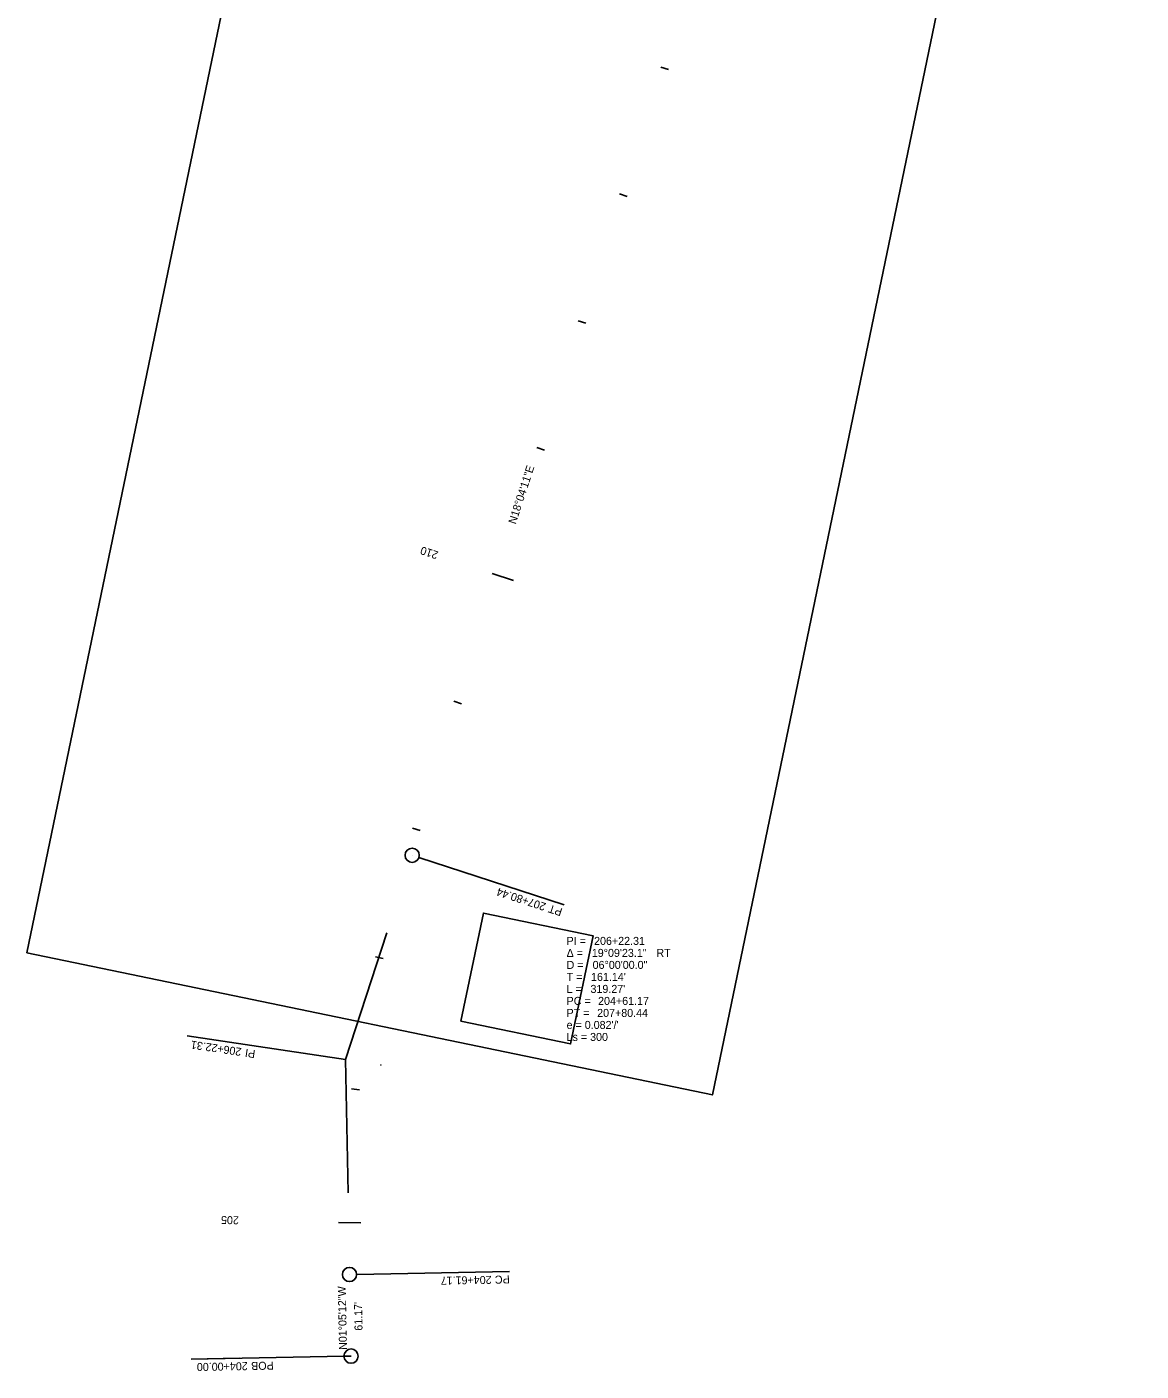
# Model space of a CAD drawing. Extents: x 1802364 to 1804577, y 572742 to 575010.
# Drawn here: x 1802960 to 1803796, y 572742 to 573749 of the extents above; entities that cross this region are included whole.
import ezdxf

# ---------------------------------------------------------------- set-up
doc = ezdxf.new("R2010")
doc.units = 0
for name, color, linetype in [('_CIVIL_CONSTRUCTION', 7, 'Continuous'), ('MOD_COR', 7, 'Continuous'), ('MOD_COR_TemplateDrop', 7, 'Continuous'), ('MOD_Points', 7, 'Continuous')]:
    doc.layers.add(name, color=color, linetype=linetype)

msp = doc.modelspace()

# ---------------------------------------------------------------- linework, layer by layer
at = {"layer": '_CIVIL_CONSTRUCTION'}
for p, q in [((1803435.4, 573719.1), (1803441.1, 573717.3)), ((1803404.4, 573624.1), (1803410.1, 573622.2)), ((1803373.4, 573529), (1803379.1, 573527.1)), ((1803342.4, 573433.9), (1803348.1, 573432.1)), ((1803309.1, 573339.6), (1803325, 573334.4)), ((1803280.3, 573243.8), (1803286, 573241.9)), ((1803249.3, 573148.7), (1803255, 573146.9)), ((1803249, 573128.3), (1803249, 573128.3)), ((1803254, 573126.6), (1803363, 573091.1)), ((1803363, 573091.1), (1803363, 573091.1)), ((1803199, 572975.1), (1803230, 573070.2)), ((1803221.4, 573052.2), (1803227.3, 573050.8)), ((1803199, 572975.1), (1803080.3, 572992.8)), ((1803080.3, 572992.8), (1803080.3, 572992.8)), ((1803199, 572975.1), (1803200.9, 572875.1)), ((1803203.5, 572953.2), (1803209.5, 572952.5)), ((1803193.7, 572853), (1803210.5, 572852.6)), ((1803202, 572814), (1803202, 572814)), ((1803207.4, 572814.1), (1803322, 572816.3)), ((1803322, 572816.3), (1803322, 572816.3)), ((1803197.9, 572752.7), (1803083.2, 572750.5)), ((1803083.2, 572750.5), (1803119.2, 572751.2)), ((1803197.2, 572752.7), (1803203.2, 572752.8)), ((1803203.2, 572752.8), (1803203.2, 572752.8))]:
    msp.add_line(p, q, dxfattribs=at)
msp.add_lwpolyline([(1803285.6, 573003.9), (1803302.4, 573085), (1803384.6, 573067.9), (1803367.8, 572986.9)], close=True, dxfattribs=at)
for centre in [(1803249, 573128.3), (1803202, 572814), (1803203.2, 572752.8)]:
    msp.add_circle(centre, 5.34, dxfattribs=at)
at = {"layer": 'MOD_COR'}
msp.add_lwpolyline([(1802960.1, 573055.2), (1803474.1, 572948.6), (1803795.6, 574499.4), (1803281.5, 574606)], close=True, dxfattribs=at)
at = {"layer": 'MOD_COR_TemplateDrop'}
msp.add_circle((1803225.5, 572971.1), 0.05, dxfattribs=at)

# ---------------------------------------------------------------- texts
at = {"layer": '_CIVIL_CONSTRUCTION'}
for s, rotation, p in [('N18°04\'11"E', 71.9303, (1803326.6, 573376.1)), ('210', 161.9303, (1803269.1, 573355.8)), ('207+80.44', 161.9303, (1803349.8, 573092.2)), ('PT', 161.9303, (1803362.1, 573088.2)), ('206+22.31', 171.5085, (1803121.3, 572983.7)), ('PI ', 171.5085, (1803131.7, 572982.1)), ('205', 178.757, (1803119.1, 572857.6)), ('204+61.17', 181.0867, (1803308.5, 572813)), ('PC', 181.0867, (1803322.1, 572813.3)), ('N01°05\'12"W', 91.0867, (1803200.1, 572757.5)), ('204+00.00', 181.0867, (1803125.6, 572748.3)), ('POB ', 181.0867, (1803145.1, 572748.7))]:
    msp.add_text(s, height=6, rotation=rotation, dxfattribs=at).set_placement(p)
for s, p in [('PI = ', (1803364.8, 573061.1)), ('206+22.31', (1803385.4, 573061.1)), ('Δ = ', (1803364.8, 573052.1)), ('19°09\'23.1"', (1803383.7, 573052.1)), (' RT', (1803429.9, 573052.1)), ('D = ', (1803364.8, 573043.1)), ('06°00\'00.0"', (1803384.3, 573043.1)), ('T = ', (1803364.8, 573034.1)), ("161.14'", (1803383.1, 573034.1)), ('L = ', (1803364.8, 573025.1)), ('PC = ', (1803364.8, 573016.1)), ("319.27'", (1803382.7, 573025.1)), ('204+61.17', (1803388.4, 573016.1)), ('PT = ', (1803364.8, 573007.1)), ('207+80.44', (1803387.7, 573007.1)), ("e = 0.082'/'", (1803364.8, 572998.1)), ('Ls = 300', (1803364.8, 572989.1))]:
    msp.add_text(s, height=6, dxfattribs=at).set_placement(p)
at = {"layer": 'MOD_Points'}
msp.add_text("61.17'", height=6, rotation=91.0867, dxfattribs=at).set_placement((1803211.8, 572771.9))

doc.saveas('drawing.dxf')
